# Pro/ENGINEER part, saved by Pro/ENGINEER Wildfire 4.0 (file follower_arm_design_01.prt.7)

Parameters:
  METRIC = "NO"

Other parameters: PITCH, DRILL_DIAMETER, THREAD_DIAMETER, THREADS_PER_INCH, THREAD_DEPTH, THREAD_LENGTH, DRILL_POINT_ANGLE, DRILL_DEPTH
